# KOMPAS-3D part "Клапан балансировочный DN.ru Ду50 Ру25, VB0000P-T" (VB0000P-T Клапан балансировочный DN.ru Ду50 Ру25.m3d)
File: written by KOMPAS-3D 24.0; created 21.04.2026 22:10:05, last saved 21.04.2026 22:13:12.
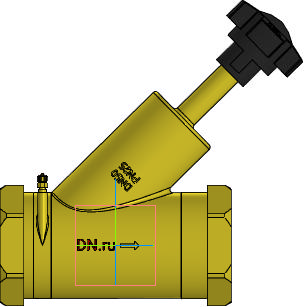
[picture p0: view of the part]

Document properties: Автор: DN.ru; Полное имя файла: E:\Работа\Зайцев\АУТСОРС\Диман\Балансировка\VB0000P-T Клапан балансировочный DN.ru Ду15-50 Ру25\DN50\VB0000P-T Клапан балансировочный DN.ru Ду50 Ру25.m3d

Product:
- Part/product: Клапан балансировочный DN.ru Ду50 Ру25  | designation VB0000P-T
    Масса: 1.9
    Раздел спецификации: Прочие изделия
    Примечание: D080-01180

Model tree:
1. Операция без истории:1

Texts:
  VB0000P-T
